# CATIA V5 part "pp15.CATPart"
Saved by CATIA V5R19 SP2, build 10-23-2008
Part number: pp15
Publications: "Line.1", "Point.3", "Point.4", "Line.2", "Line.3", "Plane.1", "Line.4", "Line.5", "Line.6", "Line.7", "Plane.2", "Plane.3"
Bounding box of the stored display mesh (mm): x -10 to 10, y -220 to 0, z -50 to 50
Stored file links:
  C:\Users\Welcome\Documents\thinkm2\pp15.CATPart
  C:\Users\Welcome\Documents\thinkm2\Brasmeca.CATProduct
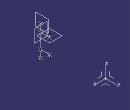
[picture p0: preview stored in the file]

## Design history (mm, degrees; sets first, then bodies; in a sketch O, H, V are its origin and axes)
AxisSystem1: origin (0, 0, 0), X (1, 0, 0), Y (0, 1, 0), Z (0, 0, 1)
Set1
  Point1 to Point4: linked copy from another document
Body1 (main body)
  Line1: type PtPt, FirstPoint Point1, SecondPoint Point2
  Point5: type OnCurve, Support Line1, Length 25
  Point6: type OnCurve, Support Line1, Length 75
  Line2: type PtPt, FirstPoint Point5, SecondPoint Point3
  Line3: type PtDir, RefPoint Point3, Direction edge [ZX plane of AxisSystem1 | YZ plane of AxisSystem1], Start 0, End 10
  Plane1: type Normal, Curve Line3
  Line4: type PtPt, FirstPoint Point6, SecondPoint Point4
  Line5: type PtDir, RefPoint Point4, Direction edge [ZX plane of AxisSystem1 | YZ plane of AxisSystem1], Start 0, End -10
  Line6: type PtDir, RefPoint Point1, Direction edge [XY plane of AxisSystem1 | ZX plane of AxisSystem1], Start 0, End -10
  Line7: type PtDir, RefPoint Point2, Direction edge [XY plane of AxisSystem1 | ZX plane of AxisSystem1], Start 0, End 10
  Plane2: type Normal, Curve Line6
  Plane3: type Normal, Curve Line2, RefPoint Point5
